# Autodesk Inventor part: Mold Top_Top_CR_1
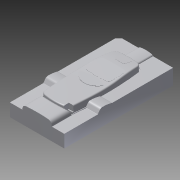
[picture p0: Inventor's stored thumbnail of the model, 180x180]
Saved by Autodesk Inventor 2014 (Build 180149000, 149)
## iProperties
Created: 2009-12
Part Number: Mold Top_Top_CR_1
Document SubType Name: Modeling
Designer: gaom
Density: 1 g/cm^3
Material: Generic
Appearance: Default
Author: gaom
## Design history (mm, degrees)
node "Mold Top_Top_CR_Base"
feature "Solid1::Mold Top_Top_CR_Base"
tag "TaggingFeature1"
body "Solid1"
